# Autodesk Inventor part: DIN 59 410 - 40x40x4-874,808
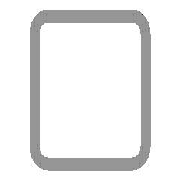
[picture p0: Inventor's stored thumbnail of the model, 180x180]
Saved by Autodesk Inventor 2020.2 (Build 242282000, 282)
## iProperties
Manager: www.cadconsulting.pl
Company: Fabian Stasiak CAD Consulting
IsCustomPart: 1
_CCFamilyMember: 20
_CCFamilyDisplayName: DIN 59410 (Kwadrat) - Rurki stalowe o przekroju kwadratowym formowane na gorąco
_FrameMemberDoc: Frame Member File
_Version: 15.0.0
_GetPNFromCC: 1
Created: 2014-02
Part Number: DIN 59 410 - 40x40x4-874,808
Material: Stal, miękka
Description: Rurki stalowe o przekroju kwadratowym formowane na gorąco
Document SubType Name: Modellieren
Standard: DIN
Designer: F.Stasiak
Standards Organization: DIN
Language: pl-PL
Size Designation: 40x40x4
Categories: <MemberInstance><Categories><Category DisplayName="Kształtowniki konstrukcyjne" InternalName="089c4875-fa83-4c05-b084-43b9cc11f5ed" Mnemonic="GRDR"><CategoryPar
Stock Number: 40x40x4
Density: 7.85 g/cm^3
Appearance: Częściowo polerowana
Mass: 3433.26 g
Surface Area: 2203.84 cm^2
Volume: 437.359 cm^3
Catalog Web Link: www.expertbooks.pl
G_W: 40,000 mm
G_H: 40,000 mm
+BF592146-D5A7-4B57-BDB9-4F7FF34067BE+CUTDETAIL1: Wytnij
+3790D512-10E6-41CA-ACF8-2A49B65F5A8A+CUTDETAIL2: Wytnij
G_L: 874,808 mm
Author: F.Stasiak
Subject: Zbiór ćwiczeń. Autodesk Inventor 2020. Kurs Professional
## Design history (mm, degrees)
node "Płaszczyzna początkowa"
node "Płaszczyzna końcowa"
sketch "Szkic1"
  geometry: L1 (-12, 20)-(12, 20); L2 (20, 12)-(20, -12); L3 (12, -20)-(-12, -20); L4 (-20, -12)-(-20, 12); L5 (-30.32, 0)-(30.32, 0) reference; L6 (0, -30.32)-(0, 30.32) reference; L7 (-12, 16)-(12, 16); L8 (16, 12)-(16, -12); L9 (12, -16)-(-12, -16); L10 (-16, -12)-(-16, 12); A1 r 8 centre (-12, 12) between (-12, 20) and (-20, 12); A2 r 8 centre (12, 12) between (20, 12) and (12, 20); A3 r 8 centre (12, -12) between (12, -20) and (20, -12); A4 r 8 centre (-12, -12) between (-20, -12) and (-12, -20); A5 r 4 centre (-12, 12) between (-12, 16) and (-16, 12); A6 r 4 centre (12, 12) between (16, 12) and (12, 16); A7 r 4 centre (12, -12) between (12, -16) and (16, -12); A8 r 4 centre (-12, -12) between (-16, -12) and (-12, -16); 3 further points
  constraints: 16 end point, 16 point on circle, 8 centre point, 8 tangent, 6 point on line, 4 parallel, 3 equal radius, 3 perpendicular, 1 horizontal, 7 other
  dimensions: "b" = 40 distance of point (-20, 20) point (20, 20); "msp_r" = 8 radius of A1 (= 2 x ParT); "d8" = 20 distance between parallel lines of L4 L6 (= d9); "d9" = 20 distance between parallel lines of L3 L5 (= 0.5 x b); "d10" = 4 distance between parallel lines of L3 L9 (= ParT)
extrude "Bryła" new body sketch "Szkic1" taper "d4" = 0 deg; stored distance "NLG" = 10
node "Driven Length"
  sketch "Sketch2"
    geometry: L1 (0, 0)-(10, 0) reference
    constraints: 2 end point, 1 horizontal
  workplane "Work Plane3"
  sketch "Sketch3"
    geometry: L1 (-2, 17.434)-(12, 17.434) reference; L2 (-2, 892.242)-(12, 892.242) reference
    dimensions: "d14" = 874.80799 distance between parallel lines of L1 L2 (derived)
node "Płaszczyzna konstrukcyjna4"
feature "Podział1"
node "Płaszczyzna konstrukcyjna5"
feature "Podział2"
body "Solid1"
other parameters: "ParT" = 4, "G_OFFSET_START" = -17.43369 [user parameter; used in 1 equation term], "G_OFFSET_END" = -25.63631 [user parameter; used in 1 equation term], "d11" = 17.43369 (= -G_OFFSET_START), "d12" = 892.24168 (= G_OFFSET_END + B_L), "G_L" = 874.80799 (= d14) [user parameter], "B_L" = 917.87799 [user parameter; used in 1 equation term], "d13" = 90 deg
